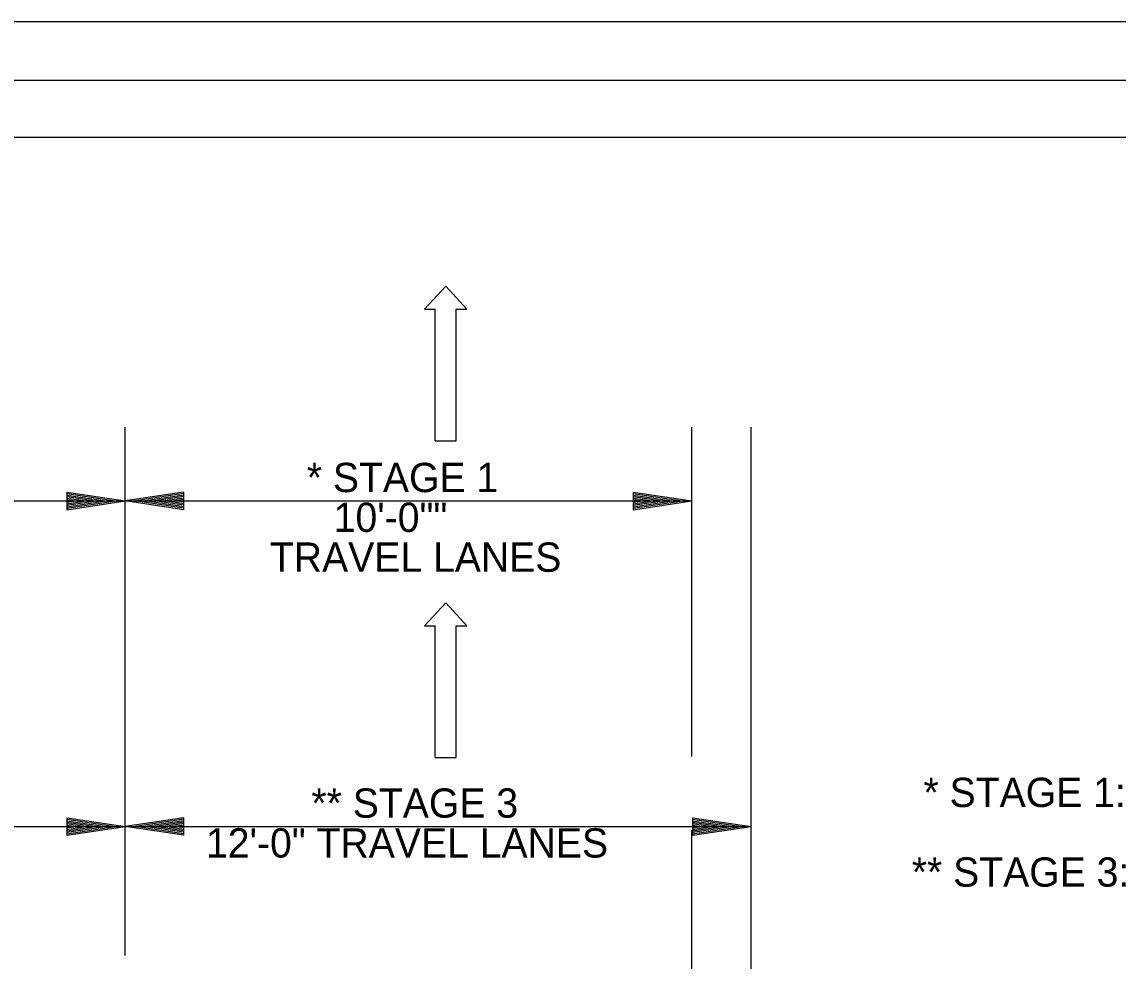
# Model space of a CAD drawing. Extents: x 6125 to 14104, y 8730 to 11067.
# Drawn here: x 8970 to 9344.5, y 10746 to 11066.7 of the extents above; entities that cross this region are included whole.
import ezdxf

# ---------------------------------------------------------------- set-up
doc = ezdxf.new("R2010")
doc.units = 0
for name, color, linetype in [('GREEN_TXT', 7, 'Continuous'), ('SEAL-INFO', 7, 'Continuous'), ('Stage 1 Construction', 7, 'Continuous')]:
    doc.layers.add(name, color=color, linetype=linetype)

msp = doc.modelspace()

# ---------------------------------------------------------------- linework, layer by layer
at = {"layer": 'GREEN_TXT'}
for p, q in [((9782.75, 11066.7), (8022.75, 11066.7)), ((8178.85, 11027.3), (9759.75, 11027.3))]:
    msp.add_line(p, q, dxfattribs=at)
at = {"layer": 'SEAL-INFO'}
msp.add_lwpolyline([(8116.81, 11046.77), (9783.51, 11046.77), (9783.51, 9980.09), (8116.81, 9980.09)], close=True, dxfattribs=at)
at = {"layer": 'Stage 1 Construction'}
for p, q in [((9111.21, 10923.62), (9111.21, 10968.59)), ((9005.34, 10747.91), (9005.34, 10928.28)), ((9198.91, 10815.82), (9198.91, 10928.28)), ((9219.18, 10637.08), (9219.18, 10928.28)), ((8985.34, 10906.15), (9005.34, 10903.15)), ((8985.34, 10906.15), (8985.34, 10900.15)), ((8985.34, 10905.65), (9002, 10903.15)), ((8985.34, 10905.14), (8998.56, 10903.15)), ((9025.34, 10906.15), (9005.34, 10903.15)), ((9025.34, 10905.65), (9008.68, 10903.15)), ((9025.34, 10905.14), (9012.12, 10903.15)), ((9025.34, 10900.15), (9025.34, 10906.15)), ((9178.91, 10906.15), (9198.91, 10903.15)), ((9178.91, 10906.15), (9178.91, 10900.15)), ((9178.91, 10905.65), (9195.57, 10903.15)), ((9178.91, 10905.14), (9192.13, 10903.15)), ((8811.77, 10903.15), (9005.34, 10903.15)), ((8985.34, 10904.64), (8995.23, 10903.15)), ((8985.34, 10904.12), (8991.84, 10903.15)), ((8985.34, 10903.62), (8988.5, 10903.15)), ((8985.34, 10900.15), (9005.34, 10903.15)), ((8985.34, 10902.17), (8991.84, 10903.15)), ((8985.34, 10901.16), (8998.56, 10903.15)), ((8985.34, 10900.65), (9002, 10903.15)), ((8985.34, 10901.66), (8995.23, 10903.15)), ((8985.34, 10902.68), (8988.5, 10903.15)), ((9025.34, 10900.15), (9005.34, 10903.15)), ((9005.34, 10903.15), (9198.91, 10903.15)), ((9025.34, 10900.65), (9008.68, 10903.15)), ((9025.34, 10901.16), (9012.12, 10903.15)), ((9025.34, 10904.64), (9015.45, 10903.15)), ((9025.34, 10901.66), (9015.45, 10903.15)), ((9025.34, 10904.13), (9018.84, 10903.15)), ((9025.34, 10902.18), (9018.84, 10903.15)), ((9025.34, 10903.62), (9022.18, 10903.15)), ((9025.34, 10902.68), (9022.18, 10903.15)), ((9178.91, 10904.64), (9188.8, 10903.15)), ((9178.91, 10904.12), (9185.41, 10903.15)), ((9178.91, 10903.62), (9182.07, 10903.15)), ((9178.91, 10900.15), (9198.91, 10903.15)), ((9178.91, 10902.17), (9185.41, 10903.15)), ((9178.91, 10901.16), (9192.13, 10903.15)), ((9178.91, 10900.65), (9195.57, 10903.15)), ((9178.91, 10901.66), (9188.8, 10903.15)), ((9178.91, 10902.68), (9182.07, 10903.15)), ((9111.21, 10815.52), (9111.21, 10860.48)), ((8985.34, 10794.97), (9005.34, 10791.97)), ((8985.34, 10794.97), (8985.34, 10788.97)), ((8985.34, 10794.47), (9002, 10791.97)), ((8985.34, 10793.96), (8998.56, 10791.97)), ((8985.34, 10793.46), (8995.23, 10791.97)), ((8985.34, 10792.94), (8991.84, 10791.97)), ((9025.34, 10794.97), (9005.34, 10791.97)), ((9025.34, 10794.47), (9008.68, 10791.97)), ((9025.34, 10793.96), (9012.12, 10791.97)), ((9025.34, 10793.46), (9015.45, 10791.97)), ((9025.34, 10792.95), (9018.84, 10791.97)), ((9025.34, 10788.97), (9025.34, 10794.97)), ((9199.18, 10794.97), (9219.18, 10791.97)), ((9199.18, 10794.97), (9199.18, 10788.97)), ((9199.18, 10794.47), (9215.84, 10791.97)), ((9199.18, 10793.96), (9212.4, 10791.97)), ((9199.18, 10793.46), (9209.07, 10791.97)), ((9199.18, 10792.94), (9205.68, 10791.97)), ((8791.5, 10791.97), (9005.34, 10791.97)), ((8985.34, 10792.44), (8988.5, 10791.97)), ((8985.34, 10788.97), (9005.34, 10791.97)), ((8985.34, 10790.99), (8991.84, 10791.97)), ((8985.34, 10789.98), (8998.56, 10791.97)), ((8985.34, 10789.47), (9002, 10791.97)), ((8985.34, 10790.48), (8995.23, 10791.97)), ((8985.34, 10791.5), (8988.5, 10791.97)), ((9025.34, 10788.97), (9005.34, 10791.97)), ((9005.34, 10791.97), (9219.18, 10791.97)), ((9025.34, 10789.47), (9008.68, 10791.97)), ((9025.34, 10789.98), (9012.12, 10791.97)), ((9025.34, 10790.48), (9015.45, 10791.97)), ((9025.34, 10791), (9018.84, 10791.97)), ((9025.34, 10792.44), (9022.18, 10791.97)), ((9025.34, 10791.5), (9022.18, 10791.97)), ((9198.91, 10660.86), (9198.91, 10790.71)), ((9199.18, 10792.44), (9202.34, 10791.97)), ((9199.18, 10788.97), (9219.18, 10791.97)), ((9199.18, 10790.99), (9205.68, 10791.97)), ((9199.18, 10789.98), (9212.4, 10791.97)), ((9199.18, 10789.47), (9215.84, 10791.97)), ((9199.18, 10790.48), (9209.07, 10791.97)), ((9199.18, 10791.5), (9202.34, 10791.97))]:
    msp.add_line(p, q, dxfattribs=at)
for points in [[(9111.21, 10923.62), (9118.41, 10923.62), (9118.41, 10968.59), (9122.01, 10968.59), (9114.81, 10976.48), (9107.61, 10968.59), (9111.21, 10968.59)], [(9111.21, 10815.52), (9118.41, 10815.52), (9118.41, 10860.48), (9122.01, 10860.48), (9114.81, 10868.38), (9107.61, 10860.48), (9111.21, 10860.48)]]:
    msp.add_lwpolyline(points, dxfattribs=at)

# ---------------------------------------------------------------- texts
for s, p in [('* STAGE 1', (9067.35, 10906.15)), ('10\'-0""', (9076.55, 10892.55)), ('TRAVEL LANES', (9054.75, 10878.95)), ('* STAGE 1: ENTIRE LENGTH', (9278.04, 10798.62)), ('** STAGE 3', (9068.94, 10794.97)), ('12\'-0" TRAVEL LANES', (9032.92, 10781.37)), ('** STAGE 3: ENTIRE LENGTH', (9274.04, 10771.42))]:
    msp.add_text(s, height=10, dxfattribs=at).set_placement(p)

doc.saveas('drawing.dxf')
